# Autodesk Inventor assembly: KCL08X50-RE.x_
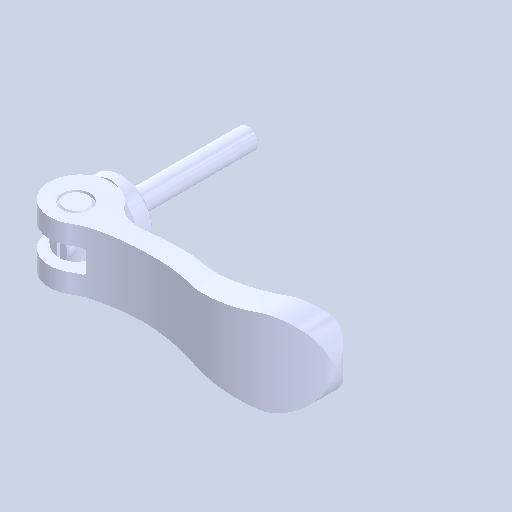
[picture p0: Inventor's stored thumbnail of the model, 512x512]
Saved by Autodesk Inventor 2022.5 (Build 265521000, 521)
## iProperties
Created: 2024-08
Part Number: KCL08X50-RE.x_
Document SubType Name: Assembly
Designer: ImaoCorp
Author: ImaoCorp
Sending System: SOLIDWORKS 2022-2022290
MC: AMD64
MC_MODEL: Intel64 Family 6 Model 60 Stepping 3, GenuineIntel
OS: Windows_NT
FRU: Parasolid Version 33.1, build 260,  4-25-2022
FORMAT: text
GUISE: transmit
KEY: FILEKCL08X50-RE.x_t
DATE: Thu Aug 29 10:50:44 2024
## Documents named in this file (5)
- Y:\5.更新分\2024年対応\1001_KCL\データ\kcl08x50-re\KCL08X50-RE.x_.iam
- Y:\5.更新分\2024年対応\1001_KCL\データ\kcl08x50-re\KCL08X50-RE_01.ipt
- Y:\5.更新分\2024年対応\1001_KCL\データ\kcl08x50-re\KCL08X50-RE_02.ipt
- Y:\5.更新分\2024年対応\1001_KCL\データ\kcl08x50-re\KCL08X50-RE_03.ipt
- Y:\5.更新分\2024年対応\1001_KCL\データ\kcl08x50-re\KCL08X50-RE_04.ipt
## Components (4 placed, 4 different names)
1. KCL08X50-RE_01
2. KCL08X50-RE_02
3. KCL08X50-RE_03
4. KCL08X50-RE_04
